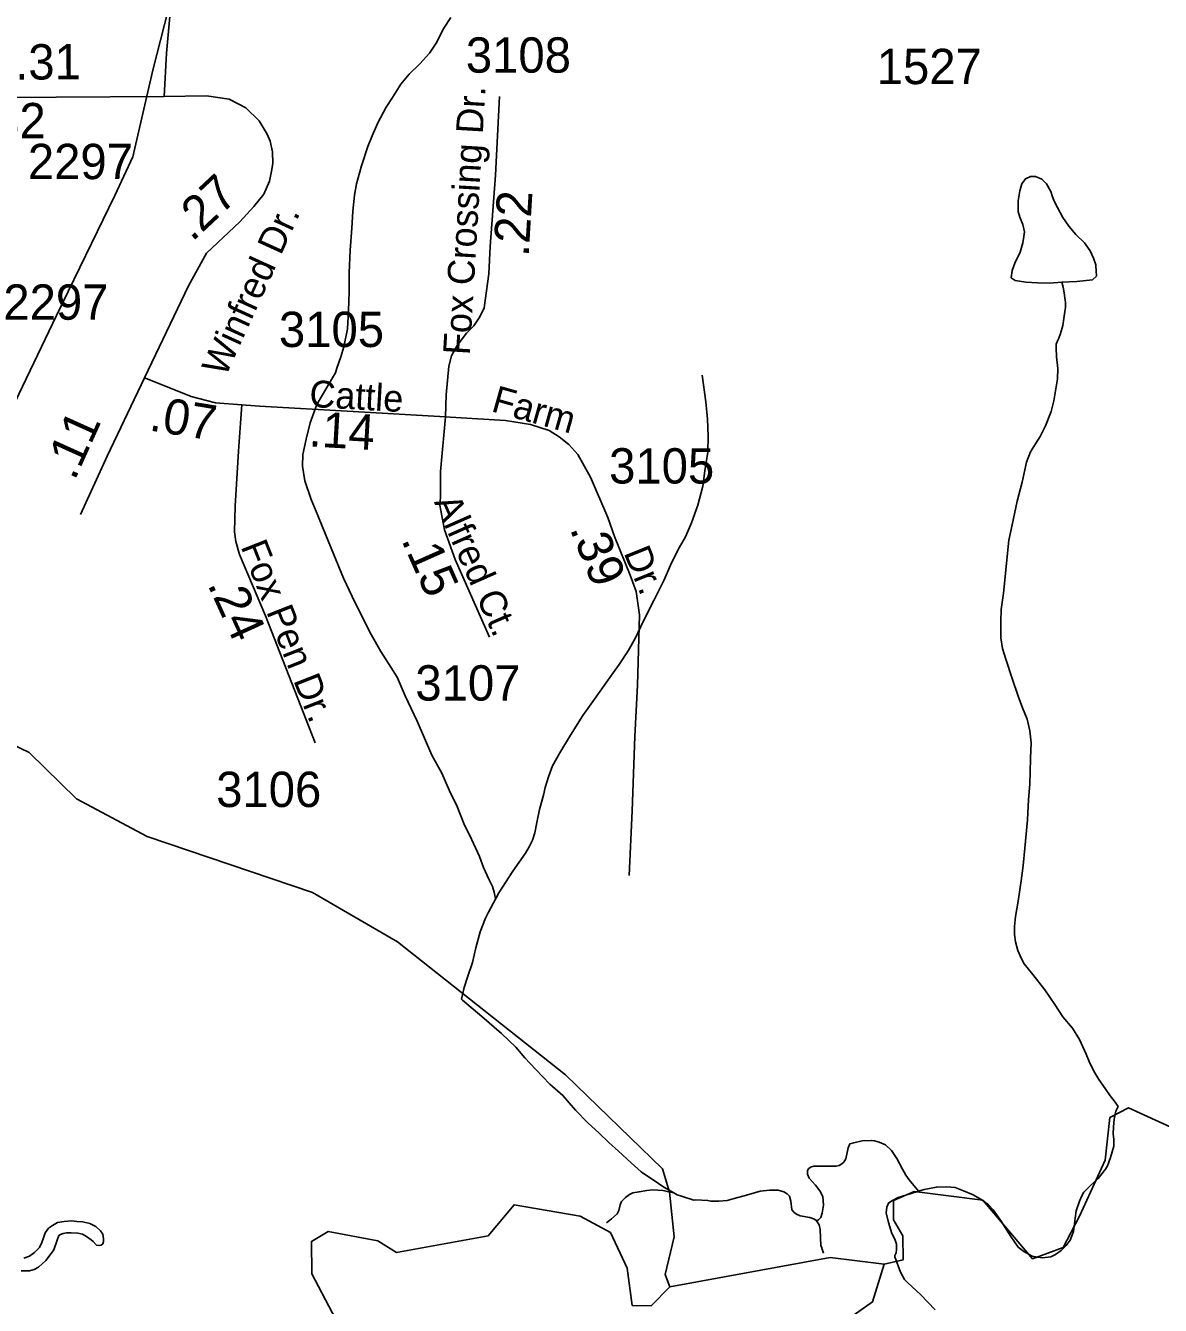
# Model space of a CAD drawing. Extents: x 2082433 to 2279600, y 546599 to 755198.
# Drawn here: x 2113702 to 2117716, y 660530 to 665057 of the extents above; entities that cross this region are included whole.
import ezdxf

# ---------------------------------------------------------------- set-up
doc = ezdxf.new("R2010")
doc.units = 0
for name, color, linetype in [('Exist Hydrographic Creek Single Shore', 7, 'Continuous'), ('Exist Hydrographic Lake Shore', 7, 'Continuous'), ('Exist Hydrographic Misc Water Feature', 7, 'Continuous'), ('Exist Road Secondary Mileage Hundredths English Label', 7, 'Continuous'), ('Exist Road Secondary Type 51 Attributed', 7, 'Continuous'), ('Exist Road Secondary Type 51 Label', 7, 'Continuous'), ('Exist Road Secondary Type 51 Number Label', 7, 'Continuous'), ('Exist Utilities Electrical Transmission Line', 7, 'Continuous')]:
    doc.layers.add(name, color=color, linetype=linetype)

msp = doc.modelspace()

# ---------------------------------------------------------------- linework, layer by layer
at = {"layer": 'Exist Hydrographic Creek Single Shore'}
msp.add_line((2116738.2, 660676.3), (2116547.3, 660699.9), dxfattribs=at)
for points in [[(2115979.3, 660931.2), (2115954.3, 661013.8), (2115611.3, 661345.5), (2115017.2, 661816.8), (2114716.4, 661990.3), (2114132.4, 662189.1), (2113882.3, 662322.2), (2113714.4, 662486.3), (2113422.4, 662626.8), (2112963.5, 662767.4), (2112622.3, 662941.2)], [(2116738.2, 660676.3), (2116805.3, 660691.3), (2116804.3, 660776.7), (2116771.2, 660833.1), (2116771.2, 660902), (2116845.3, 660933.3), (2117087.2, 660902.1), (2117263.4, 660695.2), (2117371.2, 660735.6), (2117429.3, 660846), (2117520.3, 661044.2), (2117536.3, 661194.8), (2117602.3, 661229.5), (2117819.3, 661130)], [(2115980.3, 660596.6), (2115964.4, 660639.6), (2115996.3, 660773.4), (2115979.3, 660931.2)], [(2115847.3, 660530.4), (2115914.3, 660529), (2115980.3, 660596.6)]]:
    msp.add_lwpolyline(points, dxfattribs=at)
at = {"layer": 'Exist Hydrographic Lake Shore'}
msp.add_line((2115980.3, 660596.6), (2116547.3, 660699.9), dxfattribs=at)
for points in [[(2114774.2, 660276.7), (2114807.2, 660351.5), (2114798.2, 660482.8), (2114714.4, 660642), (2114713.3, 660756.8), (2114772.4, 660791.8), (2114947.3, 660758.6), (2115013.3, 660718), (2115338.3, 660777), (2115429.4, 660886.6), (2115663.3, 660845.8), (2115771.2, 660787.9)], [(2115847.3, 660530.4), (2115830.2, 660662), (2115771.2, 660787.9)], [(2115499.3, 660143.8), (2115674.2, 660212.4), (2115773.2, 660322), (2116198.3, 660398.6), (2116223.3, 660424.4), (2116306.4, 660455.5), (2116589.4, 660466.1), (2116697.2, 660542.7), (2116738.2, 660676.3)]]:
    msp.add_lwpolyline(points, dxfattribs=at)
at = {"layer": 'Exist Hydrographic Misc Water Feature'}
msp.add_line((2116776.6, 660702.3), (2116776.4, 660706.4), dxfattribs=at)
for points in [[(2115205.9, 665086.3), (2115178.3, 665044.3), (2115156.5, 664998.1), (2115130.5, 664959.8), (2115096.7, 664922), (2115059.1, 664885.5), (2115028.8, 664849.5), (2114999.1, 664803.3), (2114977.7, 664769.2), (2114948, 664713.3), (2114927.9, 664667.3), (2114911.9, 664629.1), (2114890.4, 664561), (2114872.7, 664497.2), (2114864.9, 664457), (2114859, 664401.1), (2114855.3, 664340.8), (2114850, 664262.9), (2114845.9, 664182.8), (2114846.1, 664115), (2114844.4, 664049.2), (2114841, 663984.8), (2114827.4, 663920.8), (2114817.2, 663885), (2114803.2, 663844.9), (2114797.5, 663828.7), (2114783.7, 663804.9), (2114731.7, 663716.6), (2114708.3, 663652.5), (2114694.8, 663594.5), (2114682.9, 663540.3), (2114680.8, 663498.5), (2114689.2, 663446.5), (2114711.4, 663380.7), (2114735.8, 663324.7), (2114753.8, 663280.9), (2114790.5, 663189), (2114826.8, 663103.2), (2114856.9, 663037.4), (2114886.9, 662977.7), (2114923.6, 662903.6), (2114957.8, 662843.7), (2114993.9, 662787.9), (2115016.1, 662752.1), (2115044.6, 662686.1), (2115087, 662596.6), (2115139.3, 662476.7), (2115173.8, 662413.1), (2115201.6, 662350.9), (2115228.1, 662295.4), (2115252.5, 662235.3), (2115278.9, 662179.4), (2115306.8, 662117.6), (2115321, 662079.8), (2115341.3, 662035.7), (2115353.4, 662012), (2115359.5, 661992), (2115363.2, 661974), (2115365.5, 661970)], [(2117367.4, 664150), (2117323.7, 664145.7), (2117281.5, 664147.6), (2117239.2, 664149.5), (2117201.5, 664155.2), (2117187.6, 664165), (2117191.5, 664191.2), (2117201.3, 664217.3), (2117219.1, 664255.2), (2117229, 664289.3), (2117232.7, 664311.5), (2117234.9, 664327.4), (2117228.6, 664353.5), (2117218.5, 664379.4), (2117212.6, 664399.3), (2117212, 664437.1), (2117217.9, 664473.1), (2117225.9, 664497.5), (2117238.2, 664515.5), (2117256.1, 664523.3), (2117273.5, 664523.5), (2117296.2, 664513.6), (2117312.2, 664497.8), (2117328, 664469.8), (2117334.4, 664451.8), (2117338.3, 664439.9), (2117342, 664431.7), (2117370.5, 664377.8), (2117392.2, 664348.2), (2117416.6, 664318.2), (2117447, 664288.4), (2117466.9, 664260.2), (2117479.2, 664234.4), (2117487.2, 664210.6), (2117489, 664186.7), (2117489.2, 664174.5), (2117489.4, 664170.5), (2117475.5, 664158.4), (2117419.5, 664152.2), (2117367.4, 664150)], [(2117367.4, 664150), (2117371.5, 664131.9), (2117375.4, 664112.2), (2117377.7, 664094.1), (2117379.5, 664077.9), (2117379.5, 664060.1), (2117378.1, 664046.2)], [(2117378.1, 664046.2), (2117370.3, 663996.2), (2117362.1, 663968.2), (2117356.1, 663952.1), (2117352.6, 663944.1), (2117346.5, 663930), (2117346.5, 663917.9), (2117348.7, 663885.9), (2117352.4, 663844), (2117351.2, 663808.1), (2117343.2, 663758.2), (2117338.9, 663730), (2117329.3, 663692.1), (2117309.8, 663641.9), (2117289.9, 663603.6), (2117274.1, 663577.6), (2117256.3, 663549.9), (2117242.1, 663513.5), (2117226.3, 663441.7), (2117208.9, 663375.4), (2117191.1, 663291.7), (2117179.6, 663237.4), (2117173.8, 663179.5), (2117166, 663107.3), (2117160.1, 663049.3), (2117152.5, 662991.3), (2117150.7, 662949.4), (2117151.1, 662913.2), (2117150.9, 662891.3), (2117157.2, 662853.5), (2117169.1, 662815.6), (2117191.9, 662747.7), (2117212.2, 662685.8), (2117228.2, 662644), (2117244, 662603.9), (2117254.4, 662562.1), (2117258.9, 662520.1), (2117256.7, 662466.1), (2117254.8, 662416.1), (2117253.4, 662374.2), (2117249.5, 662320), (2117245.4, 662247.9), (2117236, 662148), (2117230.4, 662086), (2117222.6, 662032), (2117212.8, 661960.1), (2117203.4, 661905.9), (2117199.5, 661870), (2117199.5, 661842), (2117203.6, 661815.9), (2117211.4, 661785.9), (2117223.9, 661756), (2117234.1, 661738.2), (2117263.9, 661700.5), (2117306.3, 661646.6), (2117342.8, 661594.4), (2117370.7, 661550.9), (2117404.9, 661510.8), (2117429.3, 661471.1), (2117453.3, 661419.1), (2117463.6, 661393.2), (2117479.6, 661359.2), (2117497.4, 661329.3), (2117519.8, 661297.5), (2117538, 661271.6), (2117551.9, 661253.7), (2117566.1, 661233.8)], [(2116095.1, 663820.5), (2116108, 663726.5), (2116113.7, 663664.8), (2116116.2, 663604.8), (2116114.5, 663548.7), (2116104.7, 663482.5), (2116096.9, 663428.5), (2116079.3, 663360.6), (2116057.5, 663298.6), (2116035.6, 663248.4), (2116010, 663204.4), (2115982.3, 663148.1), (2115960.3, 663096.3), (2115924.5, 663023.9), (2115889, 662953.8), (2115857.6, 662889.6), (2115833.2, 662845.8), (2115801.8, 662797.4), (2115779.9, 662767.5), (2115748.3, 662723.2), (2115714.3, 662675.2), (2115672.6, 662617), (2115629.2, 662547), (2115591, 662484.6), (2115565.2, 662438.6), (2115551.7, 662400.5), (2115539.8, 662362.6), (2115533.8, 662334.7), (2115519.9, 662284.4), (2115510.2, 662238.5), (2115502.5, 662202.3), (2115494.7, 662176.3), (2115482.6, 662152.2), (2115470.5, 662130.5), (2115425.4, 662066), (2115375.3, 661990), (2115365.5, 661970)], [(2115365.5, 661970), (2115339.6, 661921.6), (2115328, 661899.8), (2115309.7, 661851.5), (2115293.9, 661795.4), (2115282.4, 661743.7), (2115266.6, 661695.4), (2115252.7, 661655.3), (2115246.8, 661629.4), (2115243.3, 661613.3)], [(2115243.3, 661613.3), (2115247.2, 661609.5), (2115315.4, 661551.7), (2115385.4, 661492), (2115435.6, 661444.3), (2115467.6, 661406.6), (2115506.1, 661364.7), (2115556.6, 661312.8), (2115602.1, 661273.1), (2115646.6, 661221.3), (2115690.9, 661175.7), (2115730.9, 661139.6), (2115765.1, 661106), (2115799.4, 661076.1), (2115843.3, 661034.1), (2115879.7, 661002.3), (2115912.6, 660980.3), (2115921.4, 660974.5), (2115912.6, 660980.3), (2115921.4, 660974.5), (2115959.5, 660948.8), (2115994.4, 660928.1), (2116006.1, 660921.1)], [(2116859.7, 660934.7), (2116879.8, 660940.9), (2116923.7, 660948.9), (2116959.3, 660949.2), (2116989.3, 660947.5), (2117019.6, 660935.6), (2117053.9, 660921.5), (2117083.6, 660903.6), (2117107.8, 660885.8), (2117124, 660867.9), (2117149.8, 660832), (2117186.1, 660774.1), (2117212.6, 660736.5), (2117232.5, 660720.5), (2117262.4, 660704.6), (2117280.5, 660700.6), (2117298.5, 660698.7), (2117328.4, 660702.7), (2117344.2, 660710.9), (2117364.5, 660724.8), (2117382.4, 660742.8), (2117395.9, 660761), (2117408.2, 660791.2), (2117414.2, 660839), (2117417.6, 660865.2), (2117429.5, 660899.1), (2117437.3, 660917.4), (2117445.1, 660931.2), (2117467.5, 660953.4), (2117495.4, 660979.6), (2117521, 661011.8), (2117529, 661023.6), (2117538.6, 661053.8), (2117550.9, 661093.7), (2117550.5, 661117.6), (2117548.5, 661137.4), (2117550.3, 661161.5), (2117551.9, 661189.6), (2117557.9, 661217.6), (2117564.3, 661229.6), (2117566.1, 661233.8)], [(2116499.8, 660829.3), (2116506, 660833.2), (2116514.2, 660841.3), (2116519.9, 660857.1), (2116523.6, 660885.4), (2116521.4, 660915.3), (2116511.5, 660935.1), (2116495.7, 660955.3), (2116473.4, 660981), (2116467.6, 660994.8), (2116467.4, 661007), (2116471.3, 661012.9), (2116477.5, 661018.9), (2116489.4, 661023.2), (2116511.3, 661023.1), (2116543.3, 661023.1), (2116569.1, 661023.3), (2116579.4, 661025.4), (2116589.2, 661031.6), (2116595.4, 661037.5), (2116603.4, 661049.3), (2116611, 661087.5), (2116617.1, 661101.6), (2116630.9, 661105.6), (2116661, 661112), (2116692.8, 661114.1), (2116704.7, 661111.9), (2116721.1, 661108.2), (2116742.8, 661098), (2116765, 661078.4), (2116783.2, 661050.5), (2116803.3, 661012.6), (2116815.4, 660990.5), (2116827.1, 660974.5), (2116855.6, 660940.6), (2116859.7, 660934.7)], [(2115756.1, 660821.9), (2115774.1, 660836.2), (2115794.2, 660854.2), (2115800, 660866.3), (2115804.3, 660886), (2115810, 660898), (2115823.8, 660912.2), (2115837.9, 660922.2), (2115849.8, 660928.1), (2115872, 660932.5), (2115899.6, 660936.4), (2115920.1, 660938.6), (2115955.8, 660936.8), (2115971.8, 660932.8), (2115994.4, 660928.1), (2116006.1, 660921.1)], [(2116065.9, 660903.1), (2116021.9, 660917.1), (2116006.1, 660921.1)], [(2116065.9, 660903.1), (2116071.9, 660903.4), (2116114.1, 660901.5), (2116125.6, 660899.4), (2116153.7, 660899.6), (2116183.8, 660901.9), (2116207.8, 660908), (2116251.9, 660920), (2116299.7, 660934.2), (2116333.5, 660938.4), (2116363.9, 660938.3), (2116383.6, 660932.5), (2116395.5, 660924.6), (2116404.1, 660916.9), (2116408.2, 660898.8), (2116411.7, 660868.7), (2116420.3, 660858.8), (2116428.1, 660852.8), (2116442, 660847), (2116475.8, 660841.1), (2116491.8, 660835), (2116499.8, 660829.3)], [(2116776.4, 660706.4), (2116780.7, 660716.3), (2116782.4, 660728.6), (2116782.4, 660746.5), (2116776.4, 660764.3), (2116766.2, 660784.2), (2116754.1, 660824.1), (2116745.7, 660858.3), (2116747.7, 660878.2), (2116753.9, 660892.3), (2116765.4, 660900.2), (2116787.9, 660912.3), (2116833.7, 660926.4), (2116859.7, 660934.7)], [(2113904.9, 660825.9), (2113928.9, 660819.8), (2113950.6, 660810), (2113966.8, 660794.2), (2113975, 660782), (2113977.1, 660766.3), (2113977.1, 660756.1), (2113974.8, 660748.4), (2113969.1, 660744), (2113961.1, 660741.9), (2113952.9, 660744), (2113941.2, 660755.9), (2113933.4, 660761.9), (2113917, 660773.8), (2113903, 660781.9), (2113887.1, 660785.6), (2113863.3, 660787.6), (2113847.1, 660787.6), (2113835.2, 660785.3), (2113825.3, 660781.6), (2113819, 660777.6), (2113813, 660761.5), (2113801.3, 660727.2), (2113789.4, 660709.5), (2113773.2, 660689.2), (2113747.6, 660665.2), (2113731.8, 660657), (2113715.4, 660653), (2113685.7, 660653.1)], [(2113695.5, 660697), (2113715.6, 660704.9), (2113733.3, 660717.2), (2113751.3, 660735.2), (2113758.9, 660753.1), (2113765, 660769.2), (2113771.4, 660787.3), (2113782.9, 660803.4), (2113797, 660813.4), (2113814.9, 660823.3), (2113838.9, 660827.3), (2113864.7, 660829.6), (2113883.2, 660827.6), (2113904.9, 660825.9)], [(2116499.8, 660829.3), (2116508.2, 660815.1), (2116512.3, 660799), (2116514.6, 660741.1), (2116516.4, 660737.2), (2116520.3, 660725.2), (2116524.6, 660715.3)], [(2116919.4, 660515.2), (2116867.1, 660568.9), (2116822.6, 660610.6), (2116810.9, 660622.4), (2116796.9, 660648.5), (2116776.6, 660702.3)]]:
    msp.add_lwpolyline(points, dxfattribs=at)
at = {"layer": 'Exist Road Secondary Type 51 Attributed'}
for points in [[(2114331.5, 667685.2), (2114324.9, 667430.5), (2114320.5, 667375.4), (2114310, 667348.4), (2114260.4, 667266.8), (2114225.9, 667179.7), (2114024.1, 666834.9), (2113985, 666754.7), (2113963.3, 666702.4), (2113957, 666686.6), (2113950.7, 666666.4), (2113945.6, 666649.3), (2113942.4, 666633.4), (2113939.6, 666619.9), (2113938.5, 666608.9), (2113938.5, 666604.9), (2113938.8, 666600.3), (2113948.3, 666536.9), (2114195.8, 665187.9), (2114212.3, 665089), (2114199.8, 664959.6), (2114191.8, 664806.8)], [(2114191.8, 664806.8), (2112853.2, 664797.7), (2112792.9, 664796.4), (2112763.3, 664795.6), (2112737.9, 664795.2), (2112711.7, 664791.6), (2112690.9, 664785.6), (2112661.7, 664775), (2112651.9, 664770.1), (2112628.1, 664752.5), (2112581.1, 664714.1)], [(2114191.8, 664806.8), (2114342.3, 664809), (2114421.8, 664797.4), (2114480.6, 664766.8), (2114528.4, 664720.2), (2114556.1, 664673.1), (2114566.4, 664647.8), (2114575, 664611), (2114576.1, 664569.7), (2114571.2, 664542.7), (2114565.1, 664507.2), (2114544.4, 664461.2), (2114508.7, 664417.6), (2114459.8, 664363), (2114342.1, 664252.6), (2114278.5, 664136.5), (2114122.9, 663811.8)], [(2115187.3, 663673.3), (2115190, 663750.9), (2115198.7, 663852.3), (2115208.2, 663888.6), (2115227.9, 663925.8), (2115261.7, 663968.8), (2115287, 663995.6), (2115309.1, 664026.5), (2115324.1, 664058.8), (2115339.9, 664178.9), (2115345.4, 664275.3), (2115363.5, 664528.2), (2115377.7, 664806.6)], [(2114122.9, 663811.8), (2113990.8, 663534), (2113896.4, 663328)], [(2114122.9, 663811.8), (2114166.9, 663793.8), (2114287, 663744.8), (2114373.8, 663723.4), (2114467.2, 663715.3)], [(2114467.2, 663715.3), (2114461.7, 663650.8), (2114455.4, 663552.1), (2114442.6, 663356.8), (2114440.4, 663266.1), (2114445.6, 663231.9), (2114458.2, 663186.3), (2114550.2, 662969), (2114726.2, 662519.7)], [(2114467.2, 663715.3), (2114529, 663711.3), (2114860.5, 663692.4), (2115187.3, 663673.3)], [(2115187.3, 663673.3), (2115169.1, 663479.5), (2115169.1, 663389.3), (2115167.6, 663360.4), (2115170.6, 663342.2), (2115183.8, 663273.8), (2115221.6, 663168.8), (2115343.2, 662894.4)], [(2115187.3, 663673.3), (2115203.8, 663672.4), (2115399.6, 663660.8), (2115488.2, 663646.3), (2115553.2, 663624.6), (2115589.4, 663602), (2115622.8, 663575.8), (2115655.3, 663539.7), (2115700.5, 663460.1), (2115761.7, 663317.7), (2115785.2, 663249.9), (2115840.2, 663113), (2115861, 663055.1), (2115872.7, 662972.9), (2115866.4, 662723.8), (2115856.4, 662543.1), (2115847.3, 662279.6), (2115836.5, 662051.3)]]:
    msp.add_lwpolyline(points, dxfattribs=at)
at = {"layer": 'Exist Utilities Electrical Transmission Line'}
msp.add_lwpolyline([(2115775.3, 671694), (2115732.3, 671513.3), (2115631.8, 670949.5), (2114899.1, 667825.5), (2114151.5, 664899), (2114080.9, 664592.8), (2114017.3, 664456.5), (2113811.3, 664031.8), (2113609.2, 663612.9), (2113421.1, 663214.4), (2113230.8, 662807.5), (2113066.3, 662458.9), (2112878.2, 662060.4), (2112715.6, 661715.7), (2112563.2, 661391.1), (2112442.4, 661132.7), (2112271.9, 660774), (2112109.6, 660433.4), (2111968.7, 660144.9), (2111828.1, 659850.4), (2111715.2, 659609.9), (2111659.8, 659481.6), (2111608.2, 659381.5)], dxfattribs=at)

# ---------------------------------------------------------------- texts
at = {"layer": 'Exist Road Secondary Mileage Hundredths English Label'}
for s, rotation, p in [('.31', 0.3912, (2113665.4, 664865.8)), ('.32', 0.2366, (2113541.1, 664657.7)), ('.27', 43.1651, (2114291, 664290.3)), ('.22', 86.6475, (2115481.1, 664237.6)), ('.07', 350.7496, (2114135.7, 663625.7)), ('.11', 65.7122, (2113875.1, 663444.8)), ('.14', 356.7383, (2114701.7, 663569)), ('.39', 292.0019, (2115625.6, 663277.7)), ('.15', 293.9058, (2115029.7, 663238.2)), ('.24', 294.5274, (2114343.9, 663080.8))]:
    msp.add_text(s, height=125, rotation=rotation, dxfattribs=at).set_placement(p)
at = {"layer": 'Exist Road Secondary Type 51 Label'}
for s, rotation, p in [('Fox Crossing Dr.', 86.6475, (2115273.1, 663890.1)), ('Winfred Dr.', 65.5199, (2114408.5, 663811.2)), ('Cattle ', 356.7383, (2114703.9, 663708.7)), ('Farm ', 344.2841, (2115345.2, 663693.8)), ('Alfred Ct.', 293.9058, (2115145.6, 663372.4)), ('Fox Pen Dr.', 291.4735, (2114461.6, 663215)), ('Dr.', 292.0019, (2115816.2, 663192.9))]:
    msp.add_text(s, height=95, rotation=rotation, dxfattribs=at).set_placement(p)
at = {"layer": 'Exist Road Secondary Type 51 Number Label'}
for s, p in [('3108', (2115259, 664890.6)), ('1527', (2116712.2, 664850.1)), ('2297', (2113709.9, 664514)), ('2297', (2113623.1, 664016.8)), ('3105', (2114597.9, 663920.2)), ('3105', (2115765.7, 663437.4)), ('3107', (2115080.4, 662669.7)), ('3106', (2114375.9, 662293.2))]:
    msp.add_text(s, height=125, dxfattribs=at).set_placement(p)

doc.saveas('drawing.dxf')
